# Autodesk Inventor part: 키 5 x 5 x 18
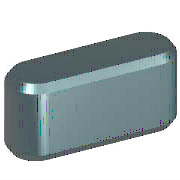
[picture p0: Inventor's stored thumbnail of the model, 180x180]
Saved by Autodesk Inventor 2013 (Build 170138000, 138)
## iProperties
Created: 2012-02
Part Number: 키 5 x 5 x 18
Material: 강철, 연강
Description: 키 및 해당 키홈
Document SubType Name: Modeling
Standard: KS B 1311
Designer: mduedu
Standards Organization: KS
Language: ko-KR
Size Designation: 5 x 5 x 18
Categories: <MemberInstance><Categories><Category DisplayName="샤프트 부품" InternalName="7f7aeb1f-a693-4053-b835-cee3144e0d98" Mnemonic="SHFT"><Category DisplayName="키" Interna
Density: 7.86 g/cm^3
Mass: 3.27476 g
Surface Area: 3.57848 cm^2
Volume: 0.416636 cm^3
IsCustomPart: 1
Author: mduedu
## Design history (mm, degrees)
workplane "Work Plane1"
workplane "Work Plane2"
sketch "스케치1"
  geometry: L1 (2.5, 2.5)-(15.5, 2.5); L2 (15.5, -2.5)-(2.5, -2.5); L3 (0, 8.9)-(0, -4.4) reference; L4 (-4, 0)-(24, 0) reference; L5 (18, 0)-(18, 7); A1 r 2.5 centre (2.5, 0) between (2.5, 2.5) and (2.5, -2.5); A2 r 2.5 centre (15.5, 0) between (15.5, -2.5) and (15.5, 2.5)
  constraints: 6 end point, 5 point on circle, 4 tangent, 3 point on line, 2 centre point, 1 horizontal, 1 parallel, 1 perpendicular
  dimensions: "d0" = 2.5 radius of A1 (= 0.5 x PB); "d13" = 2.5 radius of A2 (= 0.5 x PB); "d14" = 18 distance between parallel lines of L5 L3 (= NLG)
extrude "본체1" new body sketch "스케치1" taper "d3" = 0 deg; stored distance "d4" = 10
workplane "Work Plane3"
body "Solid1"
chamfer "모따기1" distance "d8" = 0.4 (= PHH); stored, may be unused: second distance "d9" = 0.4 (= PHH), angle "d15" = 45 deg
other parameters: "d1" = -3 (= -PNT), "d2" = 2 (= PH - PNT), "NLG" = 18 [user parameter; used in 3 equation terms], "PB" = 5 [user parameter; used in 2 equation terms], "PNT" = 3 [user parameter; used in 2 equation terms], "PH" = 5 [user parameter; used in 1 equation term], "PHH" = 0.4 [user parameter; used in 2 equation terms], "d10" = 0, "d16" = 0, "d17" = 0, "d18" = 0, "WDMIN" = 12 [user parameter], "PLB2" = 18 (= NLG) [user parameter], "WDMAX" = 17 [user parameter], "PLB1" = 18 (= NLG) [user parameter], "RR" = 0.16 [user parameter], "PUEB" = 2.3 [user parameter]
